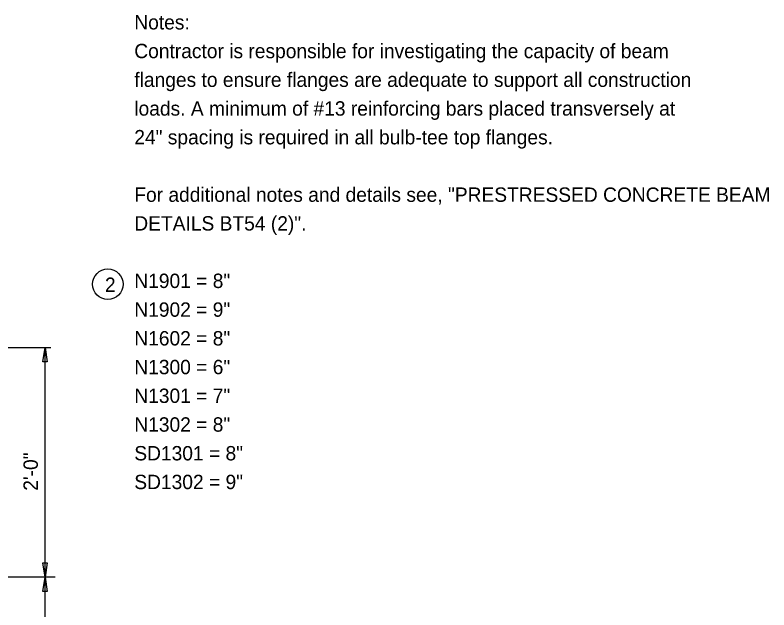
# Model space of a CAD drawing. Extents: x -125.5 to -89.3, y 42.4 to 64.4.
# Drawn here: x -105.23 to -98.67, y 48.37 to 53.54 of the extents above; entities that cross this region are included whole.
import ezdxf

# ---------------------------------------------------------------- set-up
doc = ezdxf.new("R2010")
doc.units = 0
doc.layers.add('BR_AUTO DIMENSION', color=7, linetype='Continuous')
doc.layers.add('BR_TEXT', color=7, linetype='Continuous')

msp = doc.modelspace()

# ---------------------------------------------------------------- linework, layer by layer
at = {"layer": 'BR_AUTO DIMENSION'}
for p, q in [((-105.7837, 50.6491), (-104.922, 50.6491)), ((-104.972, 49.3165), (-104.972, 50.6491)), ((-104.972, 47.8165), (-104.972, 49.3165)), ((-104.8844, 48.6498), (-105.3906, 48.6498))]:
    msp.add_line(p, q, dxfattribs=at)
for points in [[(-104.9908, 50.5241), (-104.972, 50.6491), (-104.9533, 50.5241)], [(-104.9533, 48.7748), (-104.972, 48.6498), (-104.9908, 48.7748)], [(-104.9908, 48.5248), (-104.972, 48.6498), (-104.9533, 48.5248)]]:
    msp.add_lwpolyline(points, close=True, dxfattribs=at)
at = {"layer": 'BR_TEXT'}
msp.add_circle((-104.4252, 51.1994), 0.1331, dxfattribs=at)

# ---------------------------------------------------------------- texts
at = {"layer": 'BR_AUTO DIMENSION'}
msp.add_text('2\'-0"', height=0.125, rotation=90, dxfattribs=at).set_placement((-105.0345, 49.4023))
at = {"layer": 'BR_TEXT'}
for s, p in [('Notes:', (-104.1946, 53.4163)), ('Contractor is responsible for investigating the capacity of beam', (-104.1946, 53.1663)), ('flanges to ensure flanges are adequate to support all construction ', (-104.1946, 52.9163)), ('loads. A minimum of #13 reinforcing bars placed transversely at', (-104.1946, 52.6663)), ('24" spacing is required in all bulb-tee top flanges.', (-104.1946, 52.4163)), ('For additional notes and details see, "PRESTRESSED CONCRETE BEAM ', (-104.1946, 51.9163)), ('DETAILS BT54 (2)".', (-104.1946, 51.6663)), ('N1901 = 8"', (-104.1946, 51.1663)), ('2', (-104.4502, 51.1324)), ('N1902 = 9"', (-104.1946, 50.9163)), ('N1602 = 8"', (-104.1946, 50.6663)), ('N1300 = 6"', (-104.1946, 50.4163)), ('N1301 = 7"', (-104.1946, 50.1663)), ('N1302 = 8"', (-104.1946, 49.9163)), ('SD1301 = 8"', (-104.1946, 49.6663)), ('SD1302 = 9"', (-104.1946, 49.4163))]:
    msp.add_text(s, height=0.125, dxfattribs=at).set_placement(p)

doc.saveas('drawing.dxf')
